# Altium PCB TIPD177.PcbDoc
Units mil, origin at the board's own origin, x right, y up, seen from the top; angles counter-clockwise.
Board outline 2500 x 3000 mil, 4 copper layers (Top Layer, Signal Layer 1, Signal Layer 2, Bottom Layer), stack 79.834 mil thick; 70 components, 24 nets, 146 pads, 48 vias.
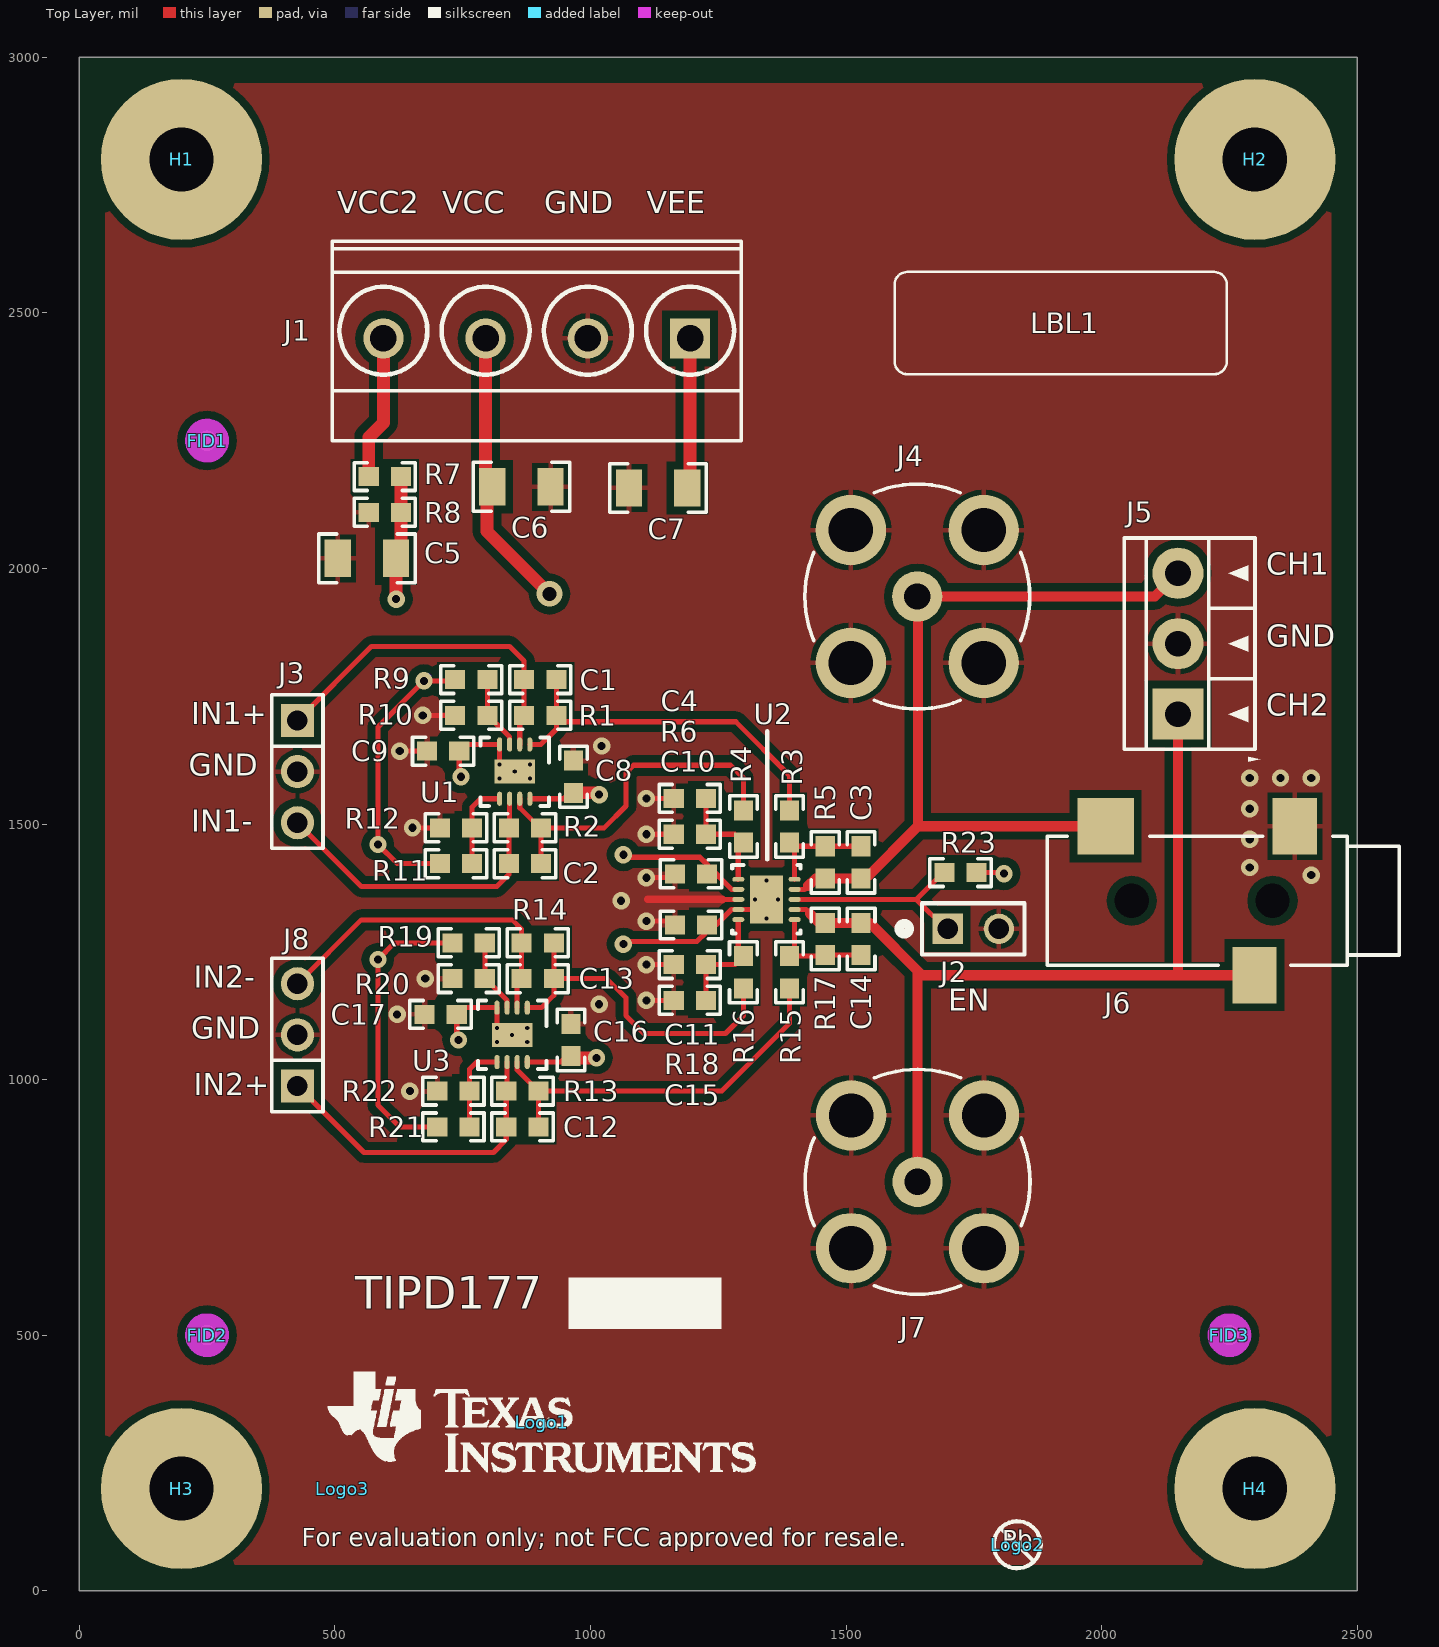
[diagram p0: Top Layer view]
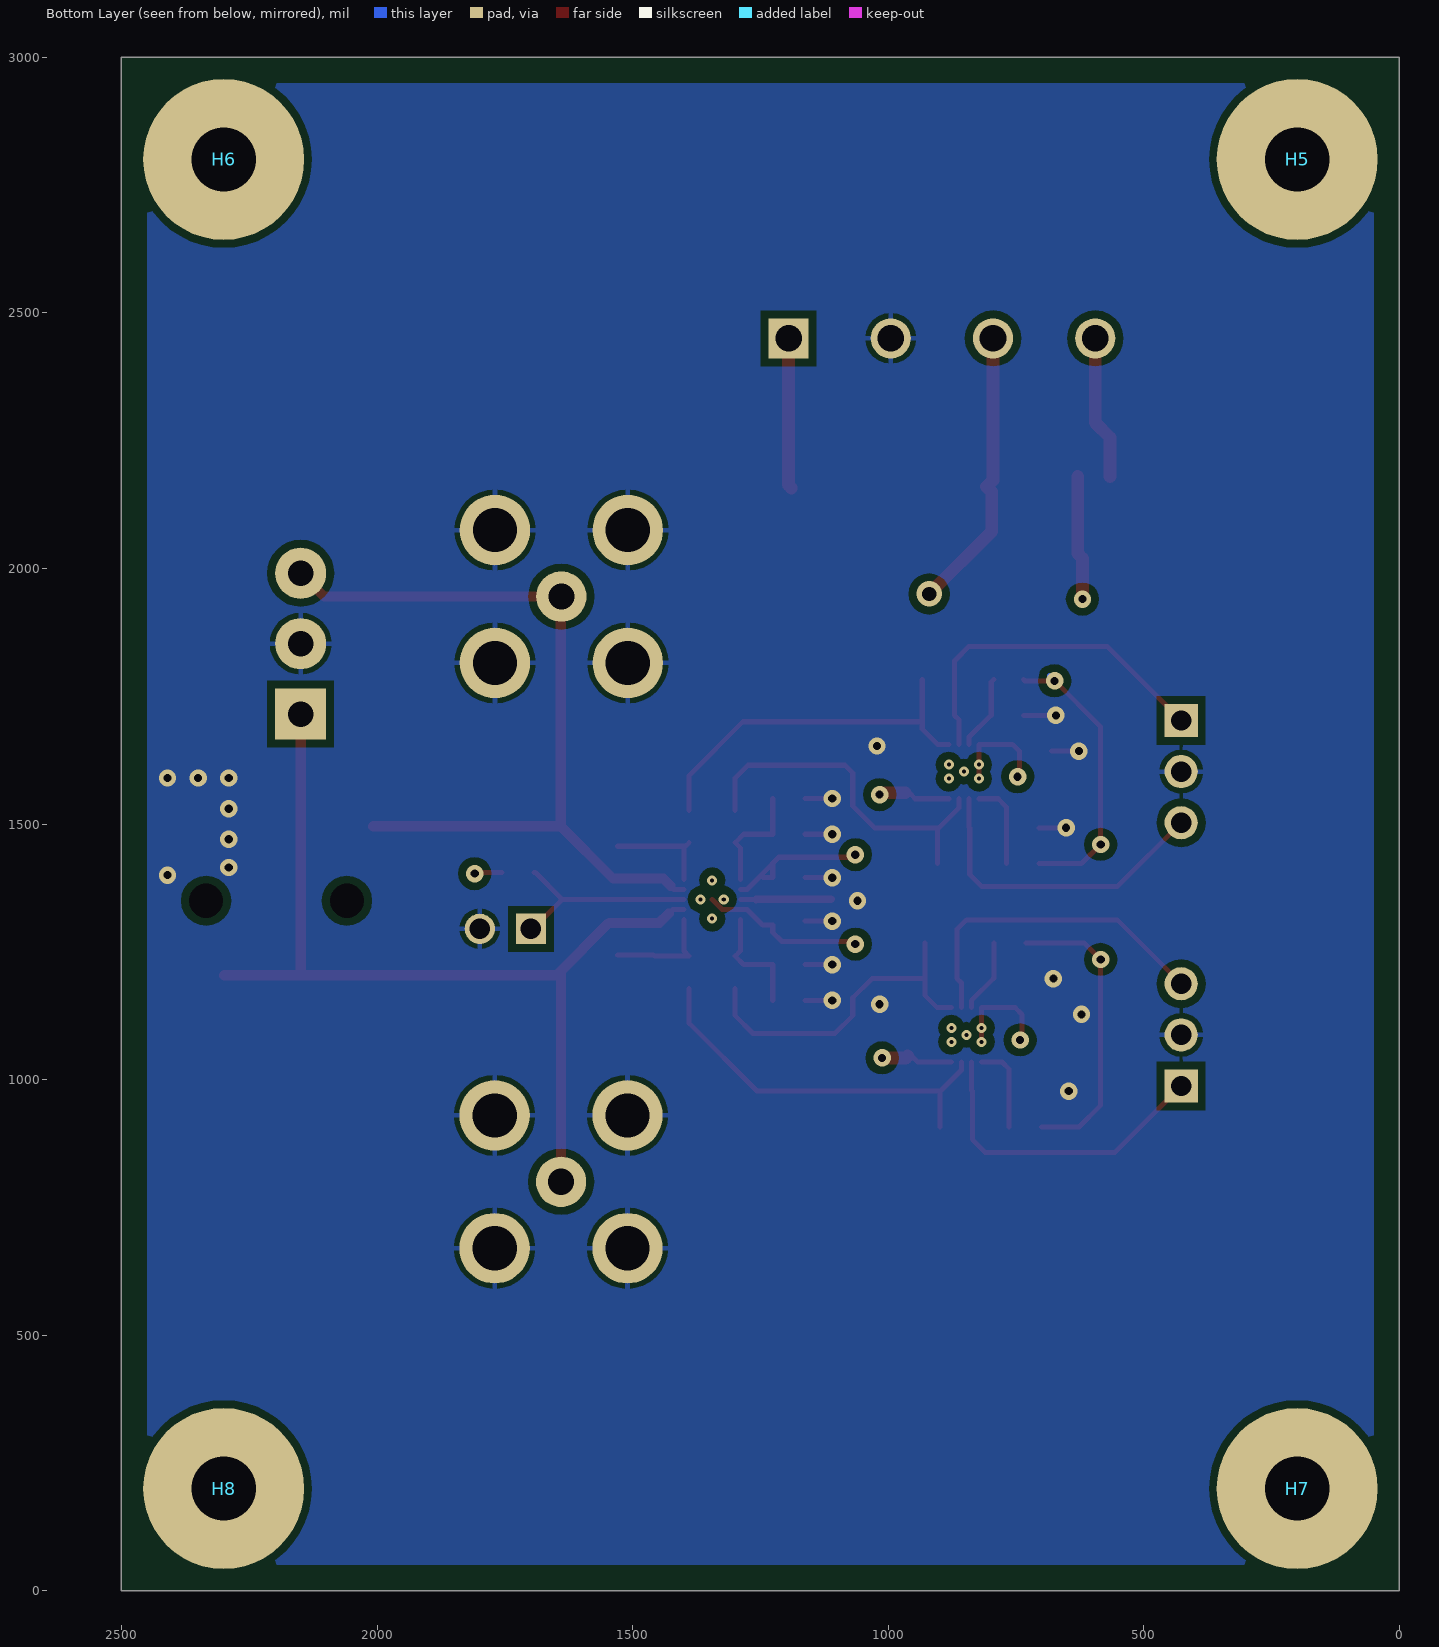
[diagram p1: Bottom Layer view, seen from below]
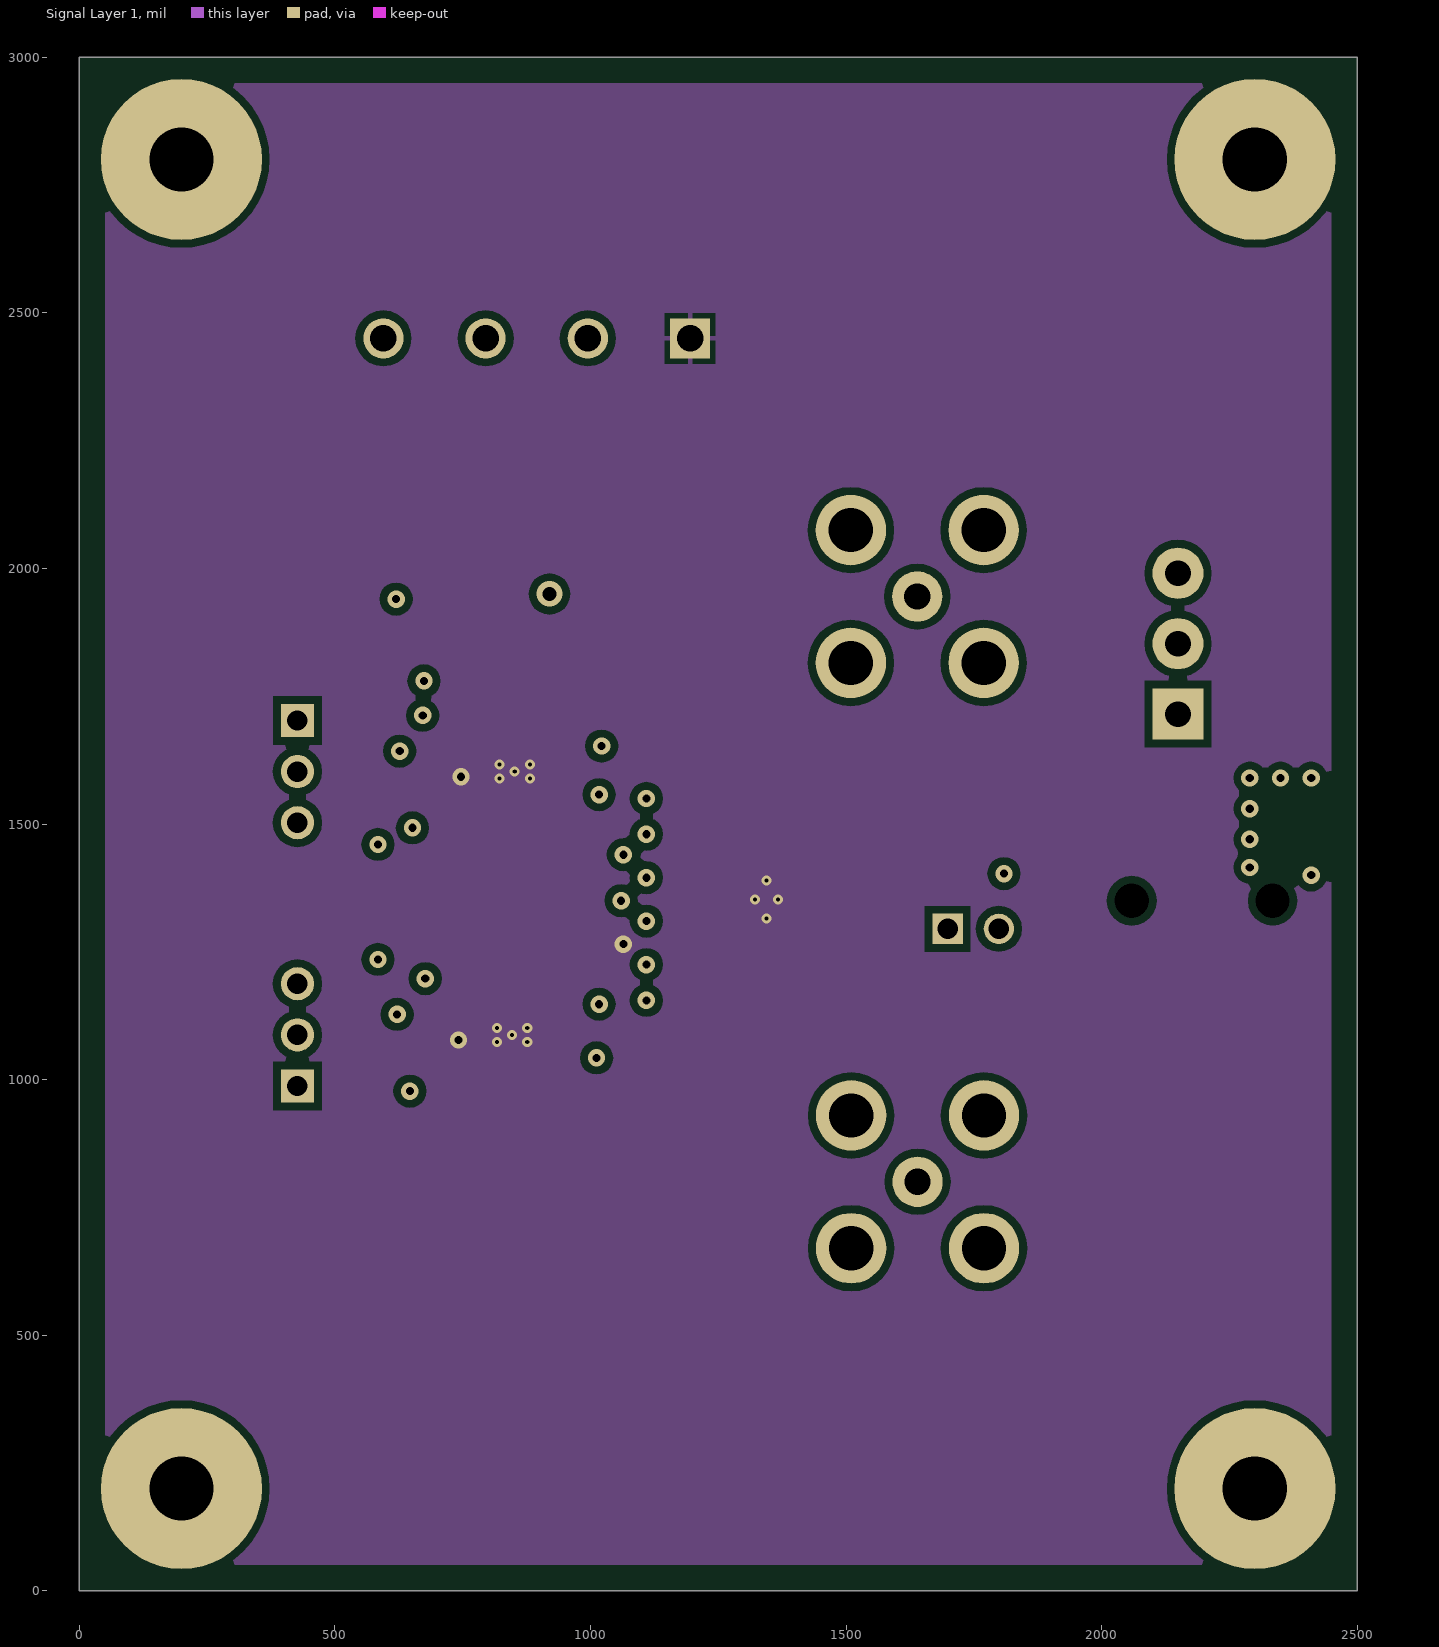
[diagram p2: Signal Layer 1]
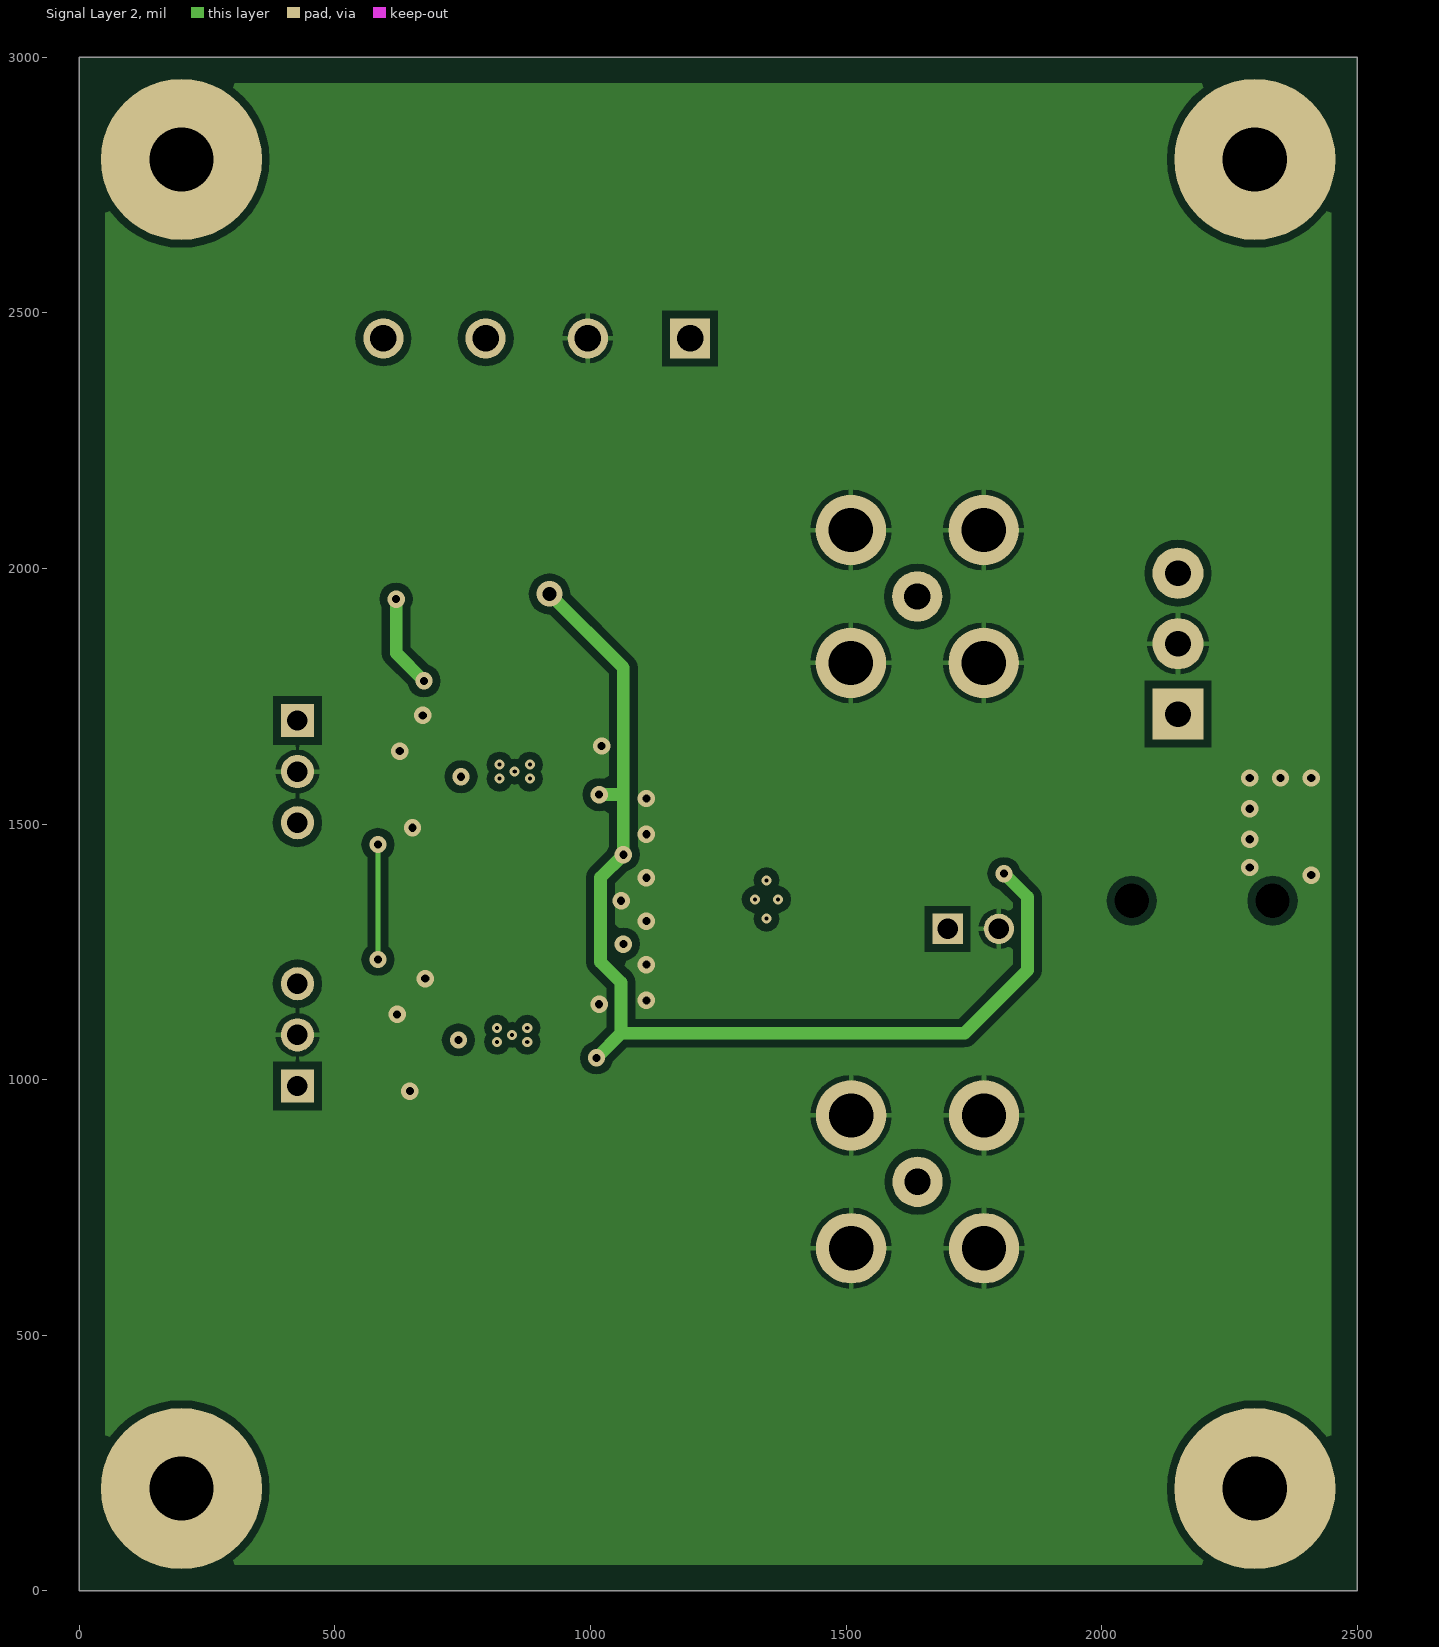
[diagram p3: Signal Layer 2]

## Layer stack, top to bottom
Top Solder: solder mask 0.4, Solder Resist, Dk 3.5
Top Layer: signal copper 1.4
Dielectric1: core 59.2, FR-4, Dk 4.8
Signal Layer 1: signal copper 1.417
Dielectric 3: prepreg 5, Dk 4.2
Signal Layer 2: signal copper 1.417
Dielectric 2: core 10, Dk 4.2
Bottom Layer: signal copper 1.4
Bottom Solder: solder mask 0.4, Solder Resist, Dk 3.5

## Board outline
0,0 0,3000 2500,3000 2500,0

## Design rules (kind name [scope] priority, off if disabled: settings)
AcuteAngle [All] p1: minimum=4.50000000000000E+0001 checktracksonly=FALSE
AssemblyTestPointUsage [All] p1: valid=2
BoardOutlineClearance BoardOutlineClearance_MountingHoles [OnCopper and InComponentClass('Mounting Holes')] p1: gap=40
BoardOutlineClearance BoardOutlineClearance_Poly [OnCopper and InPoly] p2: gap=25
BoardOutlineClearance [OnCopper and Not InComponentClass('Logo') and not InComponentClass('FiducialMark') and not InRegion(1000,500,4000,800)] p3: gap=50
Clearance Clearance_Keepouts [((IsTrack Or IsArc) And Not InPoly) And IsFree and IsKeepOut vs ((IsTrack Or IsArc) And Not InPoly) And IsFree and IsKeepOut] p1: gap=0
Clearance Clearance_Poly [InPolygon] p2: gap=15
Clearance [All] p3: gap=7.87
ComponentClearance ComponentClearance_MountingHoles_FiducialMarks [InComponentClass('Mounting Holes') vs InComponentClass('FiducialMark')] p1: gap=50 collisioncheckmode=3 verticalgap=10 showdistances=FALSE
ComponentClearance ComponentClearance_Shunt [InComponentClass('Header') vs InComponentClass('Shunt')] p2: gap=0 collisioncheckmode=3 verticalgap=0 showdistances=FALSE
ComponentClearance ComponentClearance_Logo [InComponentClass('Logo')] p3: gap=50 collisioncheckmode=3 verticalgap=10 showdistances=FALSE
ComponentClearance ComponentClearance_ScrewToNut [(HasFootprint('NY PMS 440 0025 PH')) vs (HasFootprint('Keystone_1902C'))] p4: gap=5 collisioncheckmode=3 verticalgap=10 showdistances=FALSE
ComponentClearance ComponentClearance_MountingHoles [InComponentClass('Mounting Holes')] p5: gap=100 collisioncheckmode=3 verticalgap=100000 showdistances=FALSE
ComponentClearance ComponentClearance_SmallPassives [HasFootprint('0201*') or HasFootprint('0402*') or HasFootprint('0508') or HasFootprint('0603*') or HasFootprint('0612') or HasFootprint('0805*') or HasFootprint('0815*') or HasFootprint('0830*') or HasFootprint('1206*') or HasFootprint('1210*') or HasFootprint('1808*') or HasFootprint('1812*') or HasFootprint('1825*') or HasFootprint('2010*') or HasFootprint('2220*') or HasFootprint('2225*') or HasFootprint('2512*') or HasFootprint('2728*') or HasFootprint('3518*') vs HasFootprint('0201*') or HasFootprint('0402*') or HasFootprint('0508') or HasFootprint('0603*') or HasFootprint('0612') or HasFootprint('0805*') or HasFootprint('0815*') or HasFootprint('0830*') or HasFootprint('1206*') or HasFootprint('1210*') or HasFootprint('1808*') or HasFootprint('1812*') or HasFootprint('1825*') or HasFootprint('2010*') or HasFootprint('2220*') or HasFootprint('2225*') or HasFootprint('2512*') or HasFootprint('2728*') or HasFootprint('3518*')] p6: gap=14.96 collisioncheckmode=3 verticalgap=10 showdistances=FALSE
ComponentClearance ComponentClearance_THtoSMT [IsThruComponent vs IsSMTComponent] p7: gap=40 collisioncheckmode=3 verticalgap=30 showdistances=FALSE
ComponentClearance ComponentClearance_THtoTH [IsThruComponent vs IsThruComponent] p8: gap=30 collisioncheckmode=3 verticalgap=30 showdistances=FALSE
ComponentClearance [All] p9: gap=30 collisioncheckmode=3 verticalgap=10 showdistances=FALSE
DiffPairsRouting [All] p1: maxlimit=100 minlimit=10 mostfreqgap=10 toplayer_minwidth=15 toplayer_maxwidth=15 toplayer_prefwidth=15 midlayer1_minwidth=15 midlayer1_maxwidth=15 midlayer1_prefwidth=15 midlayer2_minwidth=15 midlayer2_maxwidth=15 midlayer2_prefwidth=15 bottomlayer_minwidth=15 bottomlayer_maxwidth=15 bottomlayer_prefwidth=15 maxuncoupledlength=1000
FabricationTestPointUsage TestPointUsage [All] p1: valid=2 allowmultiple=FALSE
FabricationTestpoint Testpoint [All] p1: side=3 testpointundercomponent=TRUE minsize=40 maxsize=100 preferedsize=60 minholesize=0 maxholesize=40 preferedholesize=32 testpointgrid=1 allowsidetop=TRUE allowsidebottom=TRUE usegrid=TRUE gridtolerance=0.01
FanoutControl Fanout_LCC [IsLCC] p1: bgadir=Out bgaviamode=Centered fanoutstyle=Auto fanoutdirection=Alternating viagrid=1 // Fanout_LCC (Default Rule)
FanoutControl Fanout_BGA [IsBGA] p2: bgadir=Out bgaviamode=Centered fanoutstyle=Auto fanoutdirection=Alternating viagrid=1 // Fanout_BGA (Default Rule)
FanoutControl Fanout_Default [All] p4: bgadir=Out bgaviamode=Centered fanoutstyle=Auto fanoutdirection=Alternating viagrid=1 // Fanout_Default (Default Rule)
FanoutControl Fanout_Small [(CompPinCount < 5)] p5: bgadir=Out bgaviamode=Centered fanoutstyle=Auto fanoutdirection=OutThenIn viagrid=1 // Fanout_Small (Default Rule)
HoleSize [All] p1: absolutevalues=TRUE maxlimit=251 minlimit=7.87 maxpercent=80.000 minpercent=20.000
MinimumAnnularRing MinimumAnnularRing_ThermalPadVias [IsVia and InAnyComponent] p1: minimumring=5.91
MinimumAnnularRing [All] p2: minimumring=8
MinimumSolderMaskSliver MinimumSolderMaskSliver_Logo [InComponentClass('Logo') vs InComponentClass('Logo')] p1: minsoldermaskwidth=0.7
MinimumSolderMaskSliver [All] p2: minsoldermaskwidth=3.94
PlaneConnect [All] p1: planeconnectstyle=Relief reliefexpansion=10 reliefentries=4 reliefconductorwidth=10 reliefairgap=10
PolygonConnect PolygonConnect_2 [InComponent('U1','U2','U3')] p1: connectstyle=Direct reliefconductorwidth=10 reliefentries=4 polygonreliefangle="90 Angle" airgapwidth=10
PolygonConnect PolygonConnect_1 [InComponentClass('TIPD177_Main')] p2: connectstyle=Relief reliefconductorwidth=10 reliefentries=4 polygonreliefangle="90 Angle" airgapwidth=10
PolygonConnect [All] p3: connectstyle=Direct reliefconductorwidth=10 reliefentries=4 polygonreliefangle="90 Angle" airgapwidth=10
RoutingVias ThermalPadVias [IsVia and InAnyComponent] p1: holewidth=7.87 width=19.68 viastyle="Through Hole" minholewidth=7.87 minwidth=19.68 maxholewidth=12.99 maxwidth=23.62
RoutingVias [All] p2: holewidth=16 width=34 viastyle="Through Hole" minholewidth=7.87 minwidth=26 maxholewidth=40 maxwidth=65
SilkToBoardRegionClearance [Not ((IsComment or IsDesignator) And (Hide <> 'False')) and not InRegion(1000,500,4000,800)] p1:
SilkToSilkClearance SilkToSilkClearance_Pb-FreeLogo [(HasFootprint('Pb-Free_Overlay_Medium') OR HasFootprint('Pb-Free_Overlay_Small')) vs (HasFootprint('Pb-Free_Overlay_Medium') OR HasFootprint('Pb-Free_Overlay_Small'))] p1: silktosilkclearance=0
SilkToSilkClearance [All] p2: silktosilkclearance=4
SilkToSolderMaskClearance SilkToComponentPadClearance [IsPad and InAnycomponent] p1: minsilkscreentomaskgap=5 clearancetoexposedcopper=TRUE
SilkToSolderMaskClearance "Silk to Solder Mask Opening" [All] p2: minsilkscreentomaskgap=4 clearancetoexposedcopper=FALSE
SolderMaskExpansion [All] p1: expansion=1.97
Width [All] p1: maxlimit=100 minlimit=6 preferedwidth=10 checkconnectedcopper=TRUE
15 further rules are at their usual default settings.

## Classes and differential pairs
component class TIPD177_Main: C1 C2 C3 C4 C5 C6 C7 C8 C9 C10 C11 C12 C13 C14 C15 C16 C17 J1 J2 J3 J4 J5 J6 J7 J8 R1 R2 R3 R4 R5 R6 R7 R8 R9 R10 R11 R12 R13 R14 R15 R16 R17 R18 R19 R20 R21 R22 R23 U1 U2 U3
component class Header: J2 J3 J8
component class Label: LBL1
component class AssemblyNote: ZZ1 ZZ2 ZZ3 ZZ4
component class FiducialMark: FID1 FID2 FID3
component class TIPD177_Hardware: FID1 FID2 FID3 H1 H2 H3 H4 H5 H6 H7 H8 LBL1 Logo1 Logo2 Logo3 ZZ1 ZZ2 ZZ3 ZZ4
component class Logo: Logo1
component class "Mounting Holes": H1 H2 H3 H4

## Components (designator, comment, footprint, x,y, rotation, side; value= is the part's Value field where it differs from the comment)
C1 "GRM1885C1H101JA01D" 0603 901.93,1782.5 r180 top
C2 "GRM1885C1H101JA01D" 0603 871.93,1422.5 r180 top
C3 "GRM1885C1H561JA01D" 0603 1529.43,1425 r90 top
C4 "GRM1885C1H561JA01D" 0603 1194.43,1550 r0 top
C5 "GRM316R61E225KA12D" 1206 562.76,2019.69 r180 top
C6 "C3216X5R1C106M" 1206 865,2159.69 r0 top
C7 "C3216X5R1C106M" 1206 1132.5,2157.5 r180 top
C8 "GRM188R71H104KA93D" 0603 966.93,1592.5 r270 top
C9 "GRM188R71H104KA93D" 0603 711.93,1642.5 r0 top
C10 "GRM188R71H104KA93D" 0603 1196.93,1402.5 r180 top
C11 "GRM188R71H104KA93D" 0603 1196.93,1302.5 r180 top
C12 "GRM1885C1H101JA01D" 0603 866.93,907.5 r180 top
C13 "GRM1885C1H101JA01D" 0603 896.93,1197.5 r180 top
C14 "GRM1885C1H561JA01D" 0603 1529.43,1275 r270 top
C15 "GRM1885C1H561JA01D" 0603 1194.43,1155 r0 top
C16 "GRM188R71H104KA93D" 0603 961.93,1077.5 r270 top
C17 "GRM188R71H104KA93D" 0603 706.93,1127.5 r0 top
FID1 "Fiducial" Fiducial10-20 250,2250 r0 top
FID2 "Fiducial" Fiducial10-20 250,500 r0 top
FID3 "Fiducial" Fiducial10-20 2250,500 r0 top
H1 "NY PMS 440 0025 PH" "NY PMS 440 0025 PH" 200,2800 r0 top
H2 "NY PMS 440 0025 PH" "NY PMS 440 0025 PH" 2300,2800 r0 top
H3 "NY PMS 440 0025 PH" "NY PMS 440 0025 PH" 200,200 r0 top locked
H4 "NY PMS 440 0025 PH" "NY PMS 440 0025 PH" 2300,200 r0 top
H5 "1902C" Keystone_1902C 200,2800 r180 bottom locked
H6 "1902C" Keystone_1902C 2300,2800 r180 bottom locked
H7 "1902C" Keystone_1902C 200,200 r180 bottom locked
H8 "1902C" Keystone_1902C 2300,200 r180 bottom locked
J1 "39544-3004" MOLEX_39544-3004 895,2450 r180 top
J2 "5-146261-1" CONN_5-146261-1 1749,1295 r0 top
J3 "PBC03SAAN" PBC03SAAN 426.93,1602.5 r270 top
J4 "112404" Amphenol_112404 1639.43,1945 r0 top
J5 "ED555/3DS" TERM_BLK_ED555-3DS 2149.43,1715 r90 top
J6 "SJ-3523-SMT" CUI_SJ-3523-SMT 2192.85,1350 r180 top
J7 "112404" Amphenol_112404 1640,800 r0 top
J8 "PBC03SAAN" PBC03SAAN 426.93,1087.5 r90 top
LBL1 "Size: 0.65\" x 0.20 \"" Label_650x200 1920,2480 r0 top
Logo1 "Texas Instruments" TI_Stacked_Overlay_Small 905,330 r0 top
Logo2 "Pb-Free Symbol" Pb-Free_Overlay_Small 1835,90 r0 top
Logo3 "FCC disclaimer" FCC_disclaimer 515,200 r0 top
R1 "RT0603BRD072K32L" 0603 901.93,1712.5 r0 top
R2 "RT0603BRD072K32L" 0603 871.93,1492.5 r0 top
R3 "RT0603BRD071K58L" 0603 1389.43,1495 r270 top
R4 "RT0603BRD071K58L" 0603 1299.43,1495 r270 top
R5 "RG1608P-561-B-T5" 0603 1459.43,1425 r270 top
R6 "RG1608P-561-B-T5" 0603 1194.43,1480 r180 top
R7 "RT0603BRD0724K9L" 0603 597.76,2179.69 r180 top
R8 "RT0603BRD0714K7L" 0603 597.76,2109.69 r0 top
R9 "CRCW06030000Z0EA" 0603 766.93,1782.5 r180 top
R10 "CRCW06030000Z0EA" 0603 766.93,1712.5 r0 top
R11 "CRCW06030000Z0EA" 0603 736.93,1422.5 r180 top
R12 "CRCW06030000Z0EA" 0603 736.93,1492.5 r0 top
R13 "RT0603BRD072K32L" 0603 866.93,977.5 r0 top
R14 "RT0603BRD072K32L" 0603 896.93,1267.5 r0 top
R15 "RT0603BRD071K58L" 0603 1389.43,1210 r90 top
R16 "RT0603BRD071K58L" 0603 1299.43,1210 r90 top
R17 "RG1608P-561-B-T5" 0603 1459.43,1275 r90 top
R18 "RG1608P-561-B-T5" 0603 1194.43,1225 r180 top
R19 "CRCW06030000Z0EA" 0603 761.93,1267.5 r180 top
R20 "CRCW06030000Z0EA" 0603 761.93,1197.5 r0 top
R21 "CRCW06030000Z0EA" 0603 731.93,907.5 r180 top
R22 "CRCW06030000Z0EA" 0603 731.93,977.5 r0 top
R23 "CRCW060310K0FKEA" 0603 1724,1405 r0 top
U1 "OPA1612AIDRGR" DRG0008A 851.93,1602.5 r270 top
U2 "OPA1622IDRCR" DRC0010J 1344.43,1352.4 r0 top
U3 "OPA1612AIDRGR" DRG0008A 846.93,1087.5 r270 top
ZZ1 "This Assembly Note is for PCB labels only" AssemblyNoteLabel 185,3938 r0 top
ZZ2 "These assemblies are ESD sensitive, ESD precautions shall be observed." AssemblyNote 185,3829.11 r0 top
ZZ3 "These assemblies must be clean and free from flux and all contaminants. Use of no clean flux is not acceptable." AssemblyNote 185,3740.56 r0 top
ZZ4 "These assemblies must comply with workmanship standards IPC-A-610 Class 2, unless otherwise specified." AssemblyNote 185,3652 r0 top

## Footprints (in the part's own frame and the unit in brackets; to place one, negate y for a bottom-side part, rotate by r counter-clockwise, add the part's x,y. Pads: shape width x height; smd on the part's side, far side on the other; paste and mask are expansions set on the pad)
0603 [mm] "0603 from SM-752 data"
  rect 1x0.95 smd: 1(-0.8,0) 2(0.8,0)
  silkscreen extent -1.52,-0.69 1.52,0.69, body extent -0.87,-0.47 0.87,0.47, height 1
1206 [mm] "1206 from SM-752 data"
  rect 1.3x1.85 smd: 1(-1.45,0) 2(1.45,0)
  silkscreen extent -2.4,-1.21 2.4,1.21, body extent -1.7,-0.9 1.7,0.9, height 1.35
Amphenol_112404 [mm] "BNC footprint, pins compatible with Amp 5413631-2"
  round 2.5 hole 1.3: 1(0,0)
  round 3.5 hole 2.2: 2(-3.3,3.3) 3(3.3,3.3) 4(3.3,-3.3) 5(-3.3,-3.3)
  silkscreen extent -5.59,-5.59 5.59,5.59, body extent -5.5,-5.5 5.5,5.5, height 13.7
AssemblyNote [mil] "Assembly Note"
AssemblyNoteLabel [mil] "Assembly Note for PCB Labels"
CONN_5-146261-1 [mm] "Sullins"
  rect 1.5x1.5 hole 1.02: 1(-1.27,0)
  round 1.5 hole 1.02: 2(1.27,0)
  silkscreen extent -3.68,-1.27 2.54,1.27, body extent -2.51,-1.27 2.51,1.27, height 10.87
CUI_SJ-3523-SMT [mm] "CUI recommended land pattern Rev C CUI_SJ-3523-SMT_Datasheet.pdf"
  rect 2.2x2.8 smd: 1(-4.7,-3.7) 3(-2.7,3.7)
  rect 2.8x2.8 smd: 2(4.7,-3.7)
  round 0 hole 1.7 unplated: 4(-3.6,0) 5(3.4,0)
  silkscreen extent -9.9,-3.2 7.6,3.2, body extent -9.6,-4.5 7.4,4.5, height 5.12
DRC0010J [mm] "SON, 10-Leads, Body 3x3mm, Pitch 0.5mm, Thermal Pad 2.4x1.65mm, TI Recommended"
  rrect100% 0.6x0.24 smd: 1(-1.4,1) 2(-1.4,0.5) 3(-1.4,0) 4(-1.4,-0.5) 5(-1.4,-1) 6(1.4,-1) 7(1.4,-0.5) 8(1.4,0) 9(1.4,0.5) 10(1.4,1)
  rrect6% 1.65x2.4 smd paste-0.825: 11(0,0)
  silkscreen extent -1.7,-1.7 1.7,1.7, body extent -1.5,-1.5 1.5,1.5, height 0.77
DRG0008A [mm] "SON, 8-Leads, Body 3x3mm, Pitch 0.5mm, Thermal Pad 2x1.2mm, TI Recommended"
  oval 0.7x0.25 smd: 1(-1.35,0.75) 2(-1.35,0.25) 3(-1.35,-0.25) 4(-1.35,-0.75) 5(1.35,-0.75) 6(1.35,-0.25) 7(1.35,0.25) 8(1.35,0.75)
  rect 1.2x2 smd paste-0.6: 9(0,0)
  Drill Guide keep-out region: 0.6,-1.001 -0.6,-1.001 -0.6,-1.301 0.6,-1.301
  Drill Guide keep-out region: -0.6,0.999 0.6,0.999 0.6,1.299 -0.6,1.299
  silkscreen extent -1.7,-1.7 1.7,1.7, body extent -1.55,-1.55 1.55,1.55, height 0.81
FCC_disclaimer [mil]
Fiducial10-20 [mm]
  round 1 smd mask+0.5: 1(0,0)
  Top Layer keep-out circle w1.178: c0,0 r0.5
Keystone_1902C [mil] "Hex Standoff, 4-40 threaded, nylon"
  body extent -145,-126 146,126, height 501
Label_650x200 [mil] "Thermal Transfer Label"
  silkscreen extent -325,-100 325,100, body extent -325,-100 325,100, height 1
MOLEX_39544-3004 [mm] "Molex"
  rect 2x2 hole 1.321: 1(-7.62,0)
  round 2 hole 1.321: 2(-2.54,0) 3(2.54,0) 4(7.62,0)
  silkscreen extent -10.16,-4.83 10.16,5.08, body extent -10.16,-4.83 10.16,5.08, height 14.49
"NY PMS 440 0025 PH" [mm] "4-40 nylon screw and mounting hole"
  round 8 hole 3.2: 1(0,0)
  body extent -3.3,-3.3 3.3,3.3, height 2.69
Pb-Free_Overlay_Small [mil]
  silkscreen extent -46,-46 46,46
PBC03SAAN [mm] "Sullins 100mil, 1x3, 230 mil above insulator"
  rect 1.65x1.65 hole 1.016: 1(-2.54,0)
  round 1.65 hole 1.016: 2(0,0) 3(2.54,0)
  silkscreen extent -3.81,-1.27 3.81,1.27, body extent -3.81,-1.27 3.81,1.27, height 8.38
TERM_BLK_ED555-3DS [mm]
  rect 2.54x2.54 hole 1.27: 1(0,0)
  round 2.54 hole 1.27: 2(3.5,0) 3(7,0)
  silkscreen extent -2.36,-4.09 8.75,2.67, body extent -1.75,-3.83 8.75,2.67, height 8.2
TI_Stacked_Overlay_Small [mil]
  silkscreen extent -418,-98 418,98

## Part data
C1 C2 C12 C13: "CAP, CERM, 100 pF, 50 V, +/- 5%, C0G/NP0, 0603"
C3 C4 C14 C15: "CAP, CERM, 560 pF, 50 V, +/- 5%, C0G/NP0, 0603"
C5: "CAP, CERM, 2.2uF, 25V, +/-10%, X5R, 1206"
C6 C7: "CAP, CERM, 10uF, 16V, +/-20%, X5R, 1206"
C8 C9 C10 C11 C16 C17: "CAP, CERM, 0.1 µF, 50 V, +/- 10%, X7R, 0603"
FID1 FID2 FID3: "Fiducial mark.  There is nothing to buy or mount."
H1 H2 H3 H4: "Machine Screw, Round, #4-40 x 1/4, Nylon, Philips panhead"
H5 H6 H7 H8: "Standoff, Hex, 0.5\"L #4-40 Nylon"
J1: "Terminal Block, 4x1, 5.08mm, TH"
J2: "Header, 100mil, 2x1, Gold, TH"
J3 J8: "Header, 100mil, 3x1, Gold, TH"
J4 J7: "Connector, TH, BNC"
J5: "Terminal Block, 3.5mm Pitch, 3x1, TH"
J6: "Audio Jack, 3.5mm, Stereo, R/A, SMT"
LBL1: library part THT-14-423-10, "Thermal Transfer Printable Labels, 0.650\" W x 0.200\" H - 10,000 per roll"
Logo1: library part TI_Logo, "Texas Instrument Corporate Signature"
Logo2: library part Pb-Free
Logo3: library part FCC_disclaimer, "FCC_disclaimer"
R1 R2 R13 R14: "RES, 2.32 k, 0.1%, 0.1 W, 0603"
R3 R4 R15 R16: "RES, 1.58 k, 0.1%, 0.1 W, 0603"
R5 R6 R17 R18: "RES, 560, 0.1%, 0.1 W, 0603"
R7: "RES, 24.9 k, 0.1%, 0.1 W, 0603"
R8: "RES, 14.7 k, 0.1%, 0.1 W, 0603"
R9 R10 R11 R12 R19 R20 R21 R22: "RES, 0, 5%, 0.1 W, 0603"
R23: "RES, 10.0k ohm, 1%, 0.1W, 0603"
U1 U3: "SoundPlus High-Performance, Bipolar-Input Audio Operational Amplifiers, DRG0008A"
U2: "SoundPlus High-Fidelity, Bipolar-Input, Audio Operational Amplifier, DRC0010J"
ZZ1: library part AssemblyNoteLabel
ZZ2 ZZ3 ZZ4: library part AssemblyNote

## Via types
v1: diameter 34, hole 16, Top Layer to Bottom Layer, 33 vias
v2: diameter 19.68, hole 8, Top Layer to Bottom Layer, 14 vias
v3: diameter 50, hole 28, Top Layer to Bottom Layer, 1 vias

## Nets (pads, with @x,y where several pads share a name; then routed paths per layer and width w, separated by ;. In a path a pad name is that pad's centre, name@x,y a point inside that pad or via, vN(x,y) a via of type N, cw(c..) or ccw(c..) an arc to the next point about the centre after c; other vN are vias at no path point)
EN: J2.1 R23.1 U2.8 | length 395.9
  Top Layer w10: U2.8 1637.6,1352.4 ; R23.1 1690.2,1405 1637.6,1352.4 ; J2.1@1695,1295 1637.6,1352.4
GND: C4.1 C5.2 C6.2 C7.2 C8.1 C9.1 C10.2 C11.2 C15.1 C16.1 C17.1 J1.2 J2.2 J3.2 J4.2 J4.3 J4.4 J4.5 J5.2 J6.1 J7.2 J7.3 J7.4 J7.5 J8.2 R6.2 R8.1 R10.1 R12.1 R18.2 R20.1 R22.1 U2.3 | length 779.1
  Top Layer w10: v1(626.93,1642.5) C9.1 ; v1(651.93,1492.5) R12.1 ; v1(671.93,1712.5) R10.1 ; v1(1109.43,1155) C15.1 ; v1(1109.43,1225) R18.2 ; v1(1109.43,1310) C11.2@1162.93,1310 ; v1(1109.43,1395) C10.2@1162.93,1395 ; v1(1109.43,1480) R6.2 ; v1(1109.43,1550) C4.1 ; 1111.93,1352.5 1112.03,1352.4 1221.93,1352.4 ; 1258.02,1352.4 U2.3
  Top Layer w15: 1111.93,1352.5 1258.02,1352.4 1258.12,1352.5
  other v1: 646.93,977.5 621.93,1127.5 1016.93,1147.5 676.93,1197.5 1060,1350 2410,1400 2290,1415 2290,1470 2290,1530 2290,1590 2350,1590 2410,1590 1021.93,1652.5
NetC1_1: C1.1 R1.2 R3.1 U1.1 | length 726.5
  Top Layer w10: U1.1 903.08,1655.65 933.42,1686 R1.2 C1.1 ; R1.2@935.92,1700 1284.43,1700 1389.43,1595 R3.1
NetC1_2: C1.2 J3.1 R1.1 U1.2 | length 682.3
  Top Layer w10: J3.1 571.93,1847.5 841.93,1847.5 870.43,1819 R1.1 861.77,1703.84 U1.2
NetC2_1: C2.1 R2.2 R4.1 U1.7 | length 704.2
  Top Layer w10: U1.7 861.77,1531.66 900.93,1492.5 R2.2 ; C2.1 R2.2 ; R4.1 1299.43,1590 1274.43,1615 1084.43,1615 1069.43,1600 1069.43,1535 1026.93,1492.5 R2.2
NetC2_2: C2.2 J3.3 R2.1 U1.6 | length 624
  Top Layer w10: J3.3 551.93,1377.5 816.93,1377.5 840.43,1401 C2.2 R2.1 842.09,1494.15 U1.6
NetC3_1: C3.1 J4.1 J5.3 J6.2 R5.2 U2.9 | length 1647.3
  Top Layer w10: U2.9 1418.91,1372.09 1425.91,1379.09
  Top Layer w20: 1425.91,1379.09 1440.32,1393.5 R5.2 C3.1@1538.5,1393.5 ; C3.1 C3.1@1538.5,1393.5 ; J6.2 1640.67,1495.67 ; J5.3 2103.84,1945 J4.1 1640.67,1943.76 1640.67,1495.67 ; C3.1@1538.5,1393.5 1640.67,1495.67
NetC3_2: C3.2 R3.2 R5.1 U2.10 | length 208.9
  Top Layer w10: R3.2 R3.2@1396.44,1456.5 ; U2.10 1399.55,1453.39 R3.2@1396.44,1456.5 ; C3.2 R5.1 R3.2@1396.44,1456.5
NetC4_2: C4.2 R4.2 R6.1 U2.1 | length 226.3
  Top Layer w10: C4.2 R6.1 1282.93,1480 R4.2 1289.31,1453.39 U2.1
NetC12_1: C12.1 R13.2 R15.1 U3.7 | length 758.8
  Top Layer w10: U3.7 856.77,1018.66 897.93,977.5 R13.2 ; C12.1 R13.2 ; R15.1 1389.43,1110 1256.93,977.5 R13.2
NetC12_2: C12.2 J8.1 R13.1 U3.6 | length 625.1
  Top Layer w10: J8.1 556.93,857.5 810.19,857.5 835.43,882.74 R13.1 837.09,979.15 U3.6
NetC13_1: C13.1 R14.2 R16.1 U3.1 | length 668.6
  Top Layer w10: U3.1 904.08,1140.65 928.42,1165 C13.1 ; R14.2 C13.1 ; R16.1 1299.43,1125 1264.43,1090 1104.43,1090 1069.43,1125 1069.43,1160 1031.93,1197.5 C13.1
NetC13_2: C13.2 J8.3 R14.1 U3.2 | length 654.9
  Top Layer w10: J8.3 551.93,1312.5 846.93,1312.5 865.43,1294 R14.1 C13.2 856.77,1188.84 U3.2
NetC14_1: C14.1 J5.1 J6.3 J7.1 R17.2 U2.7 | length 1873.7
  Top Layer w10: U2.7 1421.71,1332.72 1429.43,1325 ; 2149.43,1204.9 2150,1204.33
  Top Layer w20: 1429.43,1325 1447.93,1306.5 R17.2 C14.1 1546.48,1306.5 1648.64,1204.33 2150,1204.33 J6.3 ; J7.1 1640,1210 ; 2149.43,1204.9 J5.1
NetC14_2: C14.2 R15.2 R17.1 U2.6 | length 216.6
  Top Layer w10: U2.6 1399.55,1251.61 R15.2 1457.42,1241.5 R17.1 C14.2
NetC15_2: C15.2 R16.2 R18.1 U2.5 | length 226.1
  Top Layer w10: C15.2 R18.1 1282.93,1225 R16.2 1289.31,1251.61 U2.5
NetJ1_4: J1.4 R7.2 | length 282.2
  Top Layer w25: R7.2 566.26,2256.26 595,2285 J1.4
NetR9_1: R9.1 R10.2 U1.3 | length 147.7
  Top Layer w10: R9.1@793.42,1782.5 798.42,1777.5 R10.2 799.58,1712.5 842.09,1669.99 U1.3
NetR11_1: R11.1 R12.2 U1.5 | length 171.2
  Top Layer w10: R11.1 R12.2 768.42,1533 784.78,1549.35 U1.5
NetR19_1: R19.1 R20.2 U3.3 | length 145.6
  Top Layer w10: R19.1 R20.2 794.58,1197.5 837.09,1154.99 U3.3
NetR21_1: R21.1 R22.2 U3.5 | length 172.5
  Top Layer w10: R21.1 R22.2 763.42,1020.14 777.64,1034.35 U3.5
VB: C5.1 R7.1 R8.2 R9.2 R11.2 R19.2 R21.2 | length 1799
  Top Layer w10: R21.2 626.93,907.5 584.43,950 v1(584.43,1235) 616.93,1267.5 R19.2 ; R11.2 621.93,1422.5 v1(584.43,1460) 584.43,1690 v1(674.43,1780) 732.93,1780 R9.2
  Top Layer w25: v1@619.84,1940.16 C5.1 629.25,2029.09 R8.2 R7.1
  Signal Layer 2 w10: v1(584.43,1235) v1(584.43,1460)
  Signal Layer 2 w25: v1(620,1940) 620,1834.43 v1(674.43,1780)
  Bottom Layer w10: v1(674.43,1780) v1@684.43,1790
VCC: C6.1 C8.2 C10.1 C16.2 J1.3 R23.2 U1.8 U2.2 U3.8 | length 3328.7
  Top Layer w10: U3.8 942.28,1034.35 C16.2@955.43,1047.5 ; U1.8 947.28,1549.35 C8.2@960.43,1562.5 ; v1(1064.43,1440) 1069.43,1435 1213.43,1435 ; C10.1@1244.43,1395 1225.92,1395 1225.92,1422.5 ; U2.2 1276.34,1372.09 1225.92,1422.5 ; R23.2 1807,1405 v1(1809,1403) ; 1213.43,1435 1214.43,1435 1225.92,1423.5 1225.92,1422.5 ; 1213.43,1435 1225.92,1422.5
  Top Layer w25: J1.3 795,2172.6 C6.1 797.5,2149.27 797.5,2072.5 v3(920,1950) ; C16.2 965.43,1042.5 v1(1011.93,1042.5) ; C8.2 1013.42,1561 v1(1016.93,1557.5)
  Signal Layer 2 w25: v3(920,1950) 1064.43,1805.57 1064.43,1555 ; v1(1011.93,1042.5) 1060,1090.57 ; v1(1016.93,1557.5) 1061.93,1557.5 1064.43,1555 ; v1(1809,1403) 1855,1357 1855,1214 1731.57,1090.57 1060,1090.57 ; 1060,1090.57 1060,1190 1020,1230 1020,1395.57 v1(1064.43,1440) 1064.43,1555
VEE: C7.1 C9.2 C11.1 C17.2 J1.1 U1.4 U1.9 U2.4 U2.11 U3.4 U3.9 | length 1022.6
  Top Layer w10: v1(741.93,1077.5) 738.42,1081 C17.2 751.57,1140.65 U3.4 817.4,1117.03 v2(817.4,1073.72) ; v1(746.93,1592.5) 743.42,1596 C9.2 756.57,1655.65 U1.4 822.4,1632.03 v2(822.4,1588.72) ; v1(1064.43,1265) 1069.43,1270 1207.97,1270 1225.92,1287.95 C11.1@1225.92,1302.5 ; C11.1 1245.93,1302.5 1276.15,1332.72 U2.4 1324.74,1332.72 U2.11
  Top Layer w25: C7.1 1195,2162.91 J1.1
  other v2: 876.46,1073.72 846.93,1087.5 817.4,1101.28 876.46,1101.28 1344.43,1315 1321.79,1352.4 1367.07,1352.4 1344.43,1389.8 881.46,1588.72 851.93,1602.5 822.4,1616.28 881.46,1616.28
pads on no net: FID1.1 FID2.1 FID3.1 H1.1 H2.1 H3.1 H4.1 J6.4 J6.5

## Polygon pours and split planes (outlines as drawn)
VEE on Signal Layer 1 "SIGNAL_LAYER_1_VEE_P000" (solid, remove dead copper, pour order 0): 0,3000 2500,3000 2500,0 0,0
GND on Top Layer "TOP_LAYER_GND_P006" (solid, remove dead copper, pour order 6): 0,3000 2500,3000 2500,0 0,0
GND on Bottom Layer "BOTTOM_LAYER_GND_P004" (solid, remove dead copper, pour order 4): 0,3000 2500,3000 2500,0 0,0
GND on Signal Layer 2 "SIGNAL_LAYER_2_GND_P002" (solid, remove dead copper, pour order 2): 0,3000 2500,3000 2500,0 0,0

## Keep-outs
Keep-Out Layer:
  text ".Layer_Name" at 577,-858.49 h60

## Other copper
Top Layer:
  text ".Layer_Name" at 577,-858.49 h60
Bottom Layer:
  text ".Layer_Name" at 577,-858.49 h60

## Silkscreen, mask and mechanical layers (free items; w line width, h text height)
Top Overlay:
  region: 1256.93,612.5 956.93,612.5 956.93,512.5 1256.93,512.5
  lines w8: 1345.93,1430.5 1345.93,1681.5
  text "VCC2" at 505,2680 h72.83
  text "VCC" at 710,2680 h72.83
  text "GND" at 910,2680 h72.83
  text "VEE" at 1110,2680 h72.83
  text "CH1" at 2321.93,1972.5 h72.83
  text "GND" at 2321.93,1832.5 h72.83
  text "CH2" at 2321.93,1697.5 h72.83
  text "IN1+" at 219.43,1680 h72.83
  text "GND" at 214.43,1580 h72.83
  text "IN1-" at 219.43,1470 h72.83
  text "IN2-" at 224.43,1165 h72.83
  text "EN" at 1700,1120 h72.83
  text "GND" at 219.43,1065 h72.83
  text "IN2+" at 224.43,955 h72.83
  text "TIPD177" at 540,530 h108.27
  text ".Layer_Name" at 577,-858.49 h60
Bottom Overlay:
  text ".Layer_Name" at 577,-858.49 h60
Top Paste:
  text ".Layer_Name" at 577,-858.49 h60
Bottom Paste:
  text ".Layer_Name" at 577,-858.49 h60
Top Solder:
  text ".Layer_Name" at 577,-858.49 h60
  text ".Layer_Name" at 577,-858.49 h60
Bottom Solder:
  text ".Layer_Name" at 577,-858.49 h60
Drill Guide:
  text ".Layer_Name" at 577,-858.49 h60
M1 Board Outline:
  the board outline again, w10
  text ".Layer_Name" at 577,-858.49 h60
M2 Board Dimensions:
  rectangle: 125,-400 500,-275
  rectangle: 0,-275 125,-150
  lines w7: 0,-275 1000,-275 ; 125,-400 125,-150 ; 250,-400 250,-150 ; 500,-400 500,-150 ; 750,-400 750,-150 ; 0,-400 0,-150 1000,-150 1000,-400 0,-400
  text ".Layer_Name" at 577,-858.49 h60
M3 3D STEP Top:
  text ".Layer_Name" at 577,-858.49 h60
M4 3D STEP Bottom:
  text ".Layer_Name" at 577,-858.49 h60
M5 Assembly Top:
  lines w10: -292,-930.17 6308,-930.17 ; -292,-726.83 6310,-726.83 ; -292,-523.5 -292,-1133.5 3713,-1133.5 6310,-1133.5 6310,-523.5 -291.5,-523.5 -291.5,-1133.5 1284,-1133.5 ; 2173,-1133.5 2173,-523.5 ; 3440,-726.83 3440,-523.5 ; 4280,-726.83 4280,-523.5 ; 4902,-1140 4902,-937.17
  text "COMPONENTS MARKED 'DNP' SHOULD NOT BE POPULATED." at 1153.5,-318.5 h60
  text "ASSEMBLY VARIANT:" at 1153,-434 h60
  text ".VariantName" at 2189,-434 h60
  text "PCB VIEWED FROM TOP SIDE" at -228.5,-655.67 h60
  text "BOARD #:" at 2248,-655.67 h60
  text ".PRJ_Number" at 2793.5,-655.67 h60
  text "REV:" at 3638,-655.67 h60
  text ".PCB_Rev" at 3929.5,-655.67 h60
  text "SVN REV:" at 4476,-655.67 h60
  text ".VersionControl_RevNumber" at 4982,-655.67 h60
  text "TID #:" at 2248,-859 h60
  text ".TID" at 2793.5,-859 h60
  text "PLOT NAME =" at -228.5,-1064.34 h60
  text ".plot_File_Name" at 577,-1064.34 h60
  text "GENERATED    :" at 2250,-1064.34 h60
  text ".Print_Date" at 3119.5,-1064.34 h60
  text ".Print_Time" at 3848.5,-1064.34 h60
  text "TEXAS INSTRUMENTS" at 5113,-1064.34 h60
M6 Assembly Bottom:
  lines w10: -292.5,-727.33 6309.5,-727.33 ; -290.5,-930.67 6309.5,-930.67 ; 1115.5,-1140.5 1115.5,-937.67 ; 1737.5,-727.33 1737.5,-524 ; 2577.5,-727.33 2577.5,-524 ; 3844.5,-1134 3844.5,-524 ; 4733.5,-1134 6309,-1134 6309,-524 -292.5,-524 -292.5,-1134 2304.5,-1134 6309.5,-1134 6309.5,-524
  text "COMPONENTS MARKED 'DNP' SHOULD NOT BE POPULATED." at 6102,-318 h60
  text ".VariantName" at 5058,-434 h60
  text "ASSEMBLY VARIANT:" at 6097,-434 h60
  text ".VersionControl_RevNumber" at 1035.5,-656.17 h60
  text "SVN REV:" at 1541.5,-656.17 h60
  text ".PCB_Rev" at 2088,-656.17 h60
  text "REV:" at 2379.5,-656.17 h60
  text ".PRJ_Number" at 3224,-656.17 h60
  text "BOARD #:" at 3769.5,-656.17 h60
  text "PCB VIEWED FROM BOTTOM SIDE" at 6246,-656.17 h60
  text ".TID" at 3224,-859.5 h60
  text "TID #:" at 3769.5,-859.5 h60
  text "TEXAS INSTRUMENTS" at 904.5,-1064.84 h60
  text ".Print_Time" at 2169,-1064.84 h60
  text ".Print_Date" at 2898,-1064.84 h60
  text "GENERATED    :" at 3767.5,-1064.84 h60
  text ".plot_File_Name" at 5440.5,-1064.84 h60
  text "PLOT NAME =" at 6246,-1064.84 h60
M9 Title Sheet:
  drawing of 57 lines, arcs and shapes, not listed
  text "1" at 739.84,8036.5 h70
  text "2" at 3235.5,8036.5 h70
  text "3" at 5724.84,8036.5 h70
  text "4" at 8231.51,8036.5 h70
  text "5" at 10730.5,8036.5 h70
  text "6" at 13235.5,8036.5 h70
  text "A" at -416.5,6893.5 h70
  text "A" at 14383.5,6893.5 h70
  text "B" at -416.5,4513.5 h70
  text "B" at 14383.5,4513.5 h70
  text "C" at -416.5,2138.5 h70
  text "C" at 14383.5,2138.5 h70
  text "PROJECT TITLE:" at 11343.5,277.5 h45
  text ".PRJ_Title" at 11393.5,144.17 h70
  text "DESIGNED FOR:" at 11343.5,-23.5 h45
  text ".PRJ_Customer" at 11393.5,-163.5 h70
  text "D" at -416.5,-231.5 h70
  text "D" at 14383.5,-231.5 h70
  text "FILE NAME:" at 11343.5,-323.5 h45
  text ".PCB_File_Name_No_Path" at 11393.5,-443.5 h70
  text "Texas Instruments (TI) and/or its licensors do not warrant the accuracy or completeness of this specification" at 6374,-605.34 h45
  text "ENGINEER:" at 11343.5,-613.5 h45
  text "LAYOUT BY:" at 12848.5,-613.5 h45
  text "or any information contained therein. TI and/or its licensors do not warrant that this design will meet" at 6329.01,-718 h45
  text ".PRJ_Engineer" at 11393.5,-768.49 h70
  text ".PCB_Layout" at 12899,-768.49 h70
  text "the specifications, will be suitable for your application or fit for any particular purpose, or will operate in" at 6329.01,-830.67 h45
  text ".Layer_Name" at 577,-858.49 h60
  text "ALTIUM DESIGNER VERSION:" at 12848.5,-923.5 h45
  text "an implementation. TI and/or its licensors do not warrant that the design is production worthy. You should" at 6329.01,-943.33 h45
  text "completely validate and test your design implementation to confirm the system functionality for your application." at 6374,-1056 h45
  text ".print_Scale" at 11393.5,-1056.83 h70
  text ".Application_BuildNumber" at 12899,-1056.83 h70
  text "1" at 739.84,-1263.5 h70
  text "2" at 3235.5,-1263.5 h70
  text "3" at 5724.84,-1263.5 h70
  text "4" at 8231.51,-1263.5 h70
  text "5" at 10730.5,-1263.5 h70
  text "6" at 13235.5,-1263.5 h70
M10 Fab Notes:
  drawing of 173 lines, arcs and shapes, not listed
  text "DESIGN INFORMATION" at 12378.02,6201 h60
  text "MIN. TRACK WIDTH:" at 11733.46,6021 h60
  text "8" at 12829.7,6021 h60
  text "MIL" at 12984.46,6021 h60
  text "MIN. CLEARANCE:" at 11733.46,5889 h60
  text "0.2" at 12769.7,5889 h60
  text "mm" at 12984.46,5889 h60
  text "MIN. VIA PAD SIZE:" at 11733.46,5757 h60
  text "24" at 12799.71,5757 h60
  text "MIL" at 12984.46,5757 h60
  text "0.05mm (2MIL)" at 12428.46,5615.29 h60
  text "MINIMUM ANNULAR RING" at 11404.23,5611 h60
  text "EXTERNAL" at 13136.46,5611 h60
  text "PER" at 11604.23,5493 h60
  text "IPC-D-275 CLASS 2 LEVEL C" at 11824.23,5493 h60
  text "MIL, HOLES" at 13312.46,5380.71 h60
  text "+/-" at 12920,5380 h60
  text "+/-" at 13774,5380 h60
  text "REGISTRATION TOLERANCES:" at 11404.23,5375 h60
  text "METAL" at 12604,5375 h60
  text "5" at 13180.2,5375 h60
  text "3" at 14013.2,5375 h60
  text "MIL" at 14129.46,5375 h60
  text "+/-" at 13774,5262 h60
  text "HOLE SIZE TOLERANCE (UNLESS OTHERWISE SPECIFIED):" at 11404.23,5257 h60
  text "3" at 14013.2,5257 h60
  text "MIL" at 14129.46,5257 h60
  text "MATERIAL:" at 11329.46,5047.54 h60
  text "FR-4 High Tg" at 12315.9,4907.21 h60
  text "FR-408" at 11750.46,4898.64 h60
  text "OTHER" at 13238.46,4898.64 h60
  text "X" at 12161,4895 h60
  text "62 MIL (1.6mm) +/-10%" at 12070.56,4735.92 h60
  text "THICKNESS:" at 11404.23,4731.64 h60
  text "X" at 11942.4,4731.64 h60
  text "OTHER" at 13355.46,4731.64 h60
  text "TOLERANCE:" at 11404.23,4573.64 h60
  text "X" at 12243.53,4573.64 h60
  text "ANSI IPC-6012 TYPE 3 CLASS 2" at 12430.48,4573.64 h60
  text "OTHER +/-" at 12430.46,4417.64 h60
  text "BOW & TWIST:" at 11404.23,4260.64 h60
  text "X" at 12243.53,4260.64 h60
  text "ANSI IPC-6012 TYPE 3 CLASS 2" at 12430.48,4260.64 h60
  text "OTHER +/-" at 12430.46,4102.13 h60
  text "DRILLING:" at 11329.46,3963.64 h60
  text "REFERENCE:" at 11404.23,3846.64 h60
  text "X" at 12052.46,3846.64 h60
  text "AS SHOWN" at 12239.46,3846.64 h60
  text "X" at 12953.46,3846.64 h60
  text "NC_DRILL FILES" at 13090.46,3846.64 h60
  text "PTH COPPER THICKNESS:" at 11404.23,3688.64 h60
  text "X" at 12534.46,3688.64 h60
  text "20-30 um" at 12671.46,3688.64 h60
  text "OTHER" at 13388.46,3688.64 h60
  text "BOARD FINISH:" at 11329.46,3529.64 h60
  text "SILKSCREEN:" at 11484.68,3411.64 h60
  text "X" at 12433.46,3411.64 h60
  text "TOP" at 12559.46,3411.64 h60
  text "X" at 12943.46,3411.64 h60
  text "BOTTOM" at 13070.46,3411.64 h60
  text "SILKSCREEN COLOR:" at 11484.68,3244.64 h60
  text "X" at 12432.42,3244.64 h60
  text "WHITE" at 12559.46,3244.64 h60
  text "OTHER" at 13070.46,3244.64 h60
  text "X" at 12563.42,3085.44 h60
  text "GREEN" at 12690.46,3085.44 h60
  text "OTHER" at 13308.46,3085.44 h60
  text "SOLDER RESIST COLOR:" at 11484.68,3074.64 h60
  text "X" at 12563.42,2915.44 h60
  text "MATTE" at 12690.46,2915.44 h60
  text "SEMI-GLOSS" at 13308,2914.8 h60
  text "IMMERSION GOLD (ENIG)" at 12390.46,2726.92 h60
  text "ENEPIG" at 13728,2723.64 h60
  text "SURFACE FINISH:" at 11329.46,2722.64 h60
  text "X" at 12203.51,2722.64 h60
  text "IMM. TIN/SILVER OR EQUIV" at 11659,2565.64 h60
  text "OTHER" at 13090.46,2565.64 h60
  text "ARRAY/PANEL:" at 11329.46,2386.64 h60
  text "CUT AND TRIM PER M1 BOARD OUTLINE" at 12390.46,2382.35 h60
  text "N.C. ROUTE" at 12390.46,2230.64 h60
  text "X" at 13069.46,2230.64 h60
  text "V. SCORE" at 13256.46,2230.64 h60
  text "CERTIFICATION:" at 11329.46,2093.64 h60
  text "MATERIALS AND WORKMANSHIP FOR ALL PCBS" at 12054.46,2093.64 h60
  text "TO MEET OR EXCEED THE REQUIREMENTS OF:" at 12054.46,1995.64 h60
  text "X" at 11680.96,1859.13 h60
  text "ANSI IPC-A-600F CLASS ->" at 11819.96,1859.13 h60
  text "X" at 13459.02,1859.13 h60
  text "2" at 13577.96,1859.14 h60
  text "1" at 13262.96,1857.64 h60
  text "3" at 13931.96,1857.64 h60
  text "X" at 12495.02,1699.64 h60
  text "RoHS" at 12631.96,1699.64 h60
  text "OTHER" at 13276.36,1699.64 h60
  text "PER ORDER" at 13673.42,1699.64 h60
  text "ALL BOARDS MUST MEET OR EXCEED UL94-V0 REQUIREMENTS." at 11357,1534 h60
  text "PCB MUST BEAR THE UL94V-0 UL REGISTERED MATERIAL ID NUMBER" at 11357,1414 h60
  text "ADDITIONAL REQUIREMENTS:" at 11329.46,1240.64 h60
  text "MICROSECTION:" at 11404.23,1125.64 h60
  text "YES" at 12309.96,1125.64 h60
  text "REQUIRED" at 13171.46,969.49 h60
  text "BARE BOARD ELEC. TEST:" at 11404.23,966.64 h60
  text "NONE" at 12709.96,966.64 h60
  text "X" at 13044.46,966.64 h60
  text "PER ORDER" at 13763.46,966.64 h60
  text ".Layer_Name" at 577,-858.49 h60
M11 Gerber Information:
  lines w10: -292,-930.17 6308,-930.17 ; -292,-726.83 6310,-726.83 ; -292,-523.5 -292,-1133.5 3713,-1133.5 6310,-1133.5 6310,-523.5 -291.5,-523.5 -291.5,-1133.5 1284,-1133.5 ; 2173,-1133.5 2173,-523.5 ; 3440,-726.83 3440,-523.5 ; 4280,-726.83 4280,-523.5 ; 4902,-1140 4902,-937.17
  text "ALL ARTWORK VIEWED FROM TOP SIDE" at -228.5,-655.67 h60
  text "BOARD #:" at 2248,-655.67 h60
  text ".PRJ_Number" at 2793.5,-655.67 h60
  text "REV:" at 3638,-655.67 h60
  text ".PCB_Rev" at 3929.5,-655.67 h60
  text "SVN REV:" at 4476,-655.67 h60
  text ".VersionControl_RevNumber" at 4982,-655.67 h60
  text "LAYER NAME =" at -228.5,-858.49 h60
  text "TID #:" at 2248,-859 h60
  text ".TID" at 2793.5,-859 h60
  text "PLOT NAME =" at -228.5,-1064.34 h60
  text ".plot_File_Name" at 577,-1064.34 h60
  text "GENERATED    :" at 2250,-1064.34 h60
  text ".Print_Date" at 3119.5,-1064.34 h60
  text ".Print_Time" at 3848.5,-1064.34 h60
  text "TEXAS INSTRUMENTS" at 5113,-1064.34 h60
M12 Stackup:
  drawing of 191 lines, arcs and shapes, not listed
  text "Layer" at 9790.34,7830 h60
  text "Name" at 10200.26,7830 h60
  text "Material" at 11130,7830 h60
  text "Thickness" at 11989.77,7830 h60
  text "Constant" at 12639.6,7830 h60
  text "Board Layer Stack" at 13209.46,7830 h60
  text "1" at 9790.34,7710 h60
  text "Top Overlay" at 10200.26,7710 h60
  text "2" at 9790.34,7590 h60
  text "Top Solder" at 10200.26,7590 h60
  text "Solder Resist" at 11130,7590 h60
  text "0.40mil" at 11989.77,7590 h60
  text "3.5" at 12639.6,7590 h60
  text "3" at 9790.34,7470 h60
  text "Top Layer" at 10200.26,7470 h60
  text "Copper" at 11130,7470 h60
  text "1.40mil" at 11989.77,7470 h60
  text "4" at 9790.34,7350 h60
  text "Dielectric1" at 10200.26,7350 h60
  text "FR-4" at 11130,7350 h60
  text "59.20mil" at 11989.77,7350 h60
  text "4.8" at 12639.6,7350 h60
  text "5" at 9790.34,7230 h60
  text "Bottom Layer" at 10200.26,7230 h60
  text "Copper" at 11130,7230 h60
  text "1.40mil" at 11989.77,7230 h60
  text "6" at 9790.34,7110 h60
  text "Bottom Solder" at 10200.26,7110 h60
  text "Solder Resist" at 11130,7110 h60
  text "0.40mil" at 11989.77,7110 h60
  text "3.5" at 12639.6,7110 h60
  text "7" at 9790.34,6990 h60
  text "Bottom Overlay" at 10200.26,6990 h60
  text ".Layer_Name" at 577,-858.49 h60
M13 Component Bodies Top:
  text ".Layer_Name" at 577,-858.49 h60
M14 Component Bodies Bottom:
  text ".Layer_Name" at 577,-858.49 h60
M15 Courtyards Top:
  text ".Layer_Name" at 577,-858.49 h60
M16 Courtyards Bottom:
  text ".Layer_Name" at 577,-858.49 h60
Drill Drawing:
  circle w10: c2915.55,2087.86 r13.28
  circle w10: c2915.55,2087.86 r22.14
  circle w10: c2915.55,1390.5 r22.14
  lines w10: 2893.41,1467.98 2915.55,1479.05 2937.69,1467.98 2926.62,1490.12 2937.69,1512.26 2915.55,1501.19 2893.41,1512.26 2904.48,1490.12 2893.41,1467.98 ; 2893.41,1567.61 2937.69,1567.61 2937.69,1611.88 2893.41,1611.88 2893.41,1567.61 ; 2893.41,1678.3 2904.48,1678.3 2915.55,1667.23 2926.62,1678.3 2937.69,1678.3 2926.62,1689.37 2937.69,1700.44 2926.62,1700.44 2915.55,1711.51 2904.48,1700.44 2893.41,1700.44 2904.48,1689.37 2893.41,1678.3 ; 2893.41,1777.92 2904.48,1777.92 2904.48,1766.85 2926.62,1766.85 2926.62,1777.92 2937.69,1777.92 2937.69,1800.06 2926.62,1800.06 2926.62,1811.13 2904.48,1811.13 2904.48,1800.06 2893.41,1800.06 2893.41,1777.92 ; 2893.41,1910.75 2937.69,1910.75 2915.55,1866.47 2893.41,1910.75 ; 2893.41,2010.37 2937.69,2010.37 2915.55,1966.1 2893.41,2010.37 ; 2893.41,2165.34 2937.69,2165.34 2937.69,2209.62 2893.41,2209.62 2893.41,2165.34 ; 2893.41,2276.03 2904.48,2276.03 2915.55,2264.96 2926.62,2276.03 2937.69,2276.03 2926.62,2287.1 2937.69,2298.17 2926.62,2298.17 2915.55,2309.24 2904.48,2298.17 2893.41,2298.17 2904.48,2287.1 2893.41,2276.03 ; 2893.41,2364.59 2893.41,2375.66 2904.48,2386.72 2893.41,2397.79 2893.41,2408.86 2904.48,2408.86 2915.55,2397.79 2926.62,2408.86 2937.69,2408.86 2937.69,2397.79 2926.62,2386.72 2937.69,2375.66 2937.69,2364.59 2926.62,2364.59 2915.55,2375.66 2904.48,2364.59 2893.41,2364.59 ; 2902.26,1901.9 2928.83,1901.9 2915.55,1875.33 2902.26,1901.9 ; 2902.26,2174.2 2928.83,2174.2 2928.83,2200.76 2902.26,2200.76 2902.26,2174.2 ; 2902.26,2280.46 2908.91,2280.46 2915.55,2273.82 2922.19,2280.46 2928.83,2280.46 2922.19,2287.1 2928.83,2293.74 2922.19,2293.74 2915.55,2300.38 2908.91,2293.74 2902.26,2293.74 2908.91,2287.1 2902.26,2280.46
  lines w12: 2852.65,1338.48 5965.59,1338.48 ; 2852.65,2434.32 5965.59,2434.32 ; 3168.28,1238.85 3168.28,2533.94 ; 3485.47,1238.85 3485.47,2533.94 ; 4107.21,1238.85 4107.21,2533.94 ; 4351.53,1238.85 4351.53,2533.94 ; 4711.87,1238.85 4711.87,2533.94 ; 5421.38,1238.85 5421.38,2533.94 ; 2852.65,1238.85 5965.59,1238.85 5965.59,2533.94 2852.65,2533.94 2852.65,1238.85
  text "Symbol" at 2912.42,2464.21 h72
  text "Quantity" at 3198.17,2464.21 h72
  text "Finished Hole Size" at 3515.35,2464.21 h72
  text "Plated" at 4137.1,2464.21 h72
  text "Hole Type" at 4381.42,2464.21 h72
  text "Drill Layer Pair" at 4741.76,2464.21 h72
  text "Hole Tolerance" at 5451.27,2464.21 h72
  text "2" at 3198.17,2364.59 h60
  text "66.93mil (1.700mm)" at 3515.35,2364.59 h60
  text "NPTH" at 4137.1,2364.59 h60
  text "Round" at 4381.42,2364.59 h60
  text "Top Layer - Bottom Layer" at 4741.76,2364.59 h60
  text "14" at 3198.17,2264.96 h60
  text "8.00mil (0.203mm)" at 3515.35,2264.96 h60
  text "PTH" at 4137.1,2264.96 h60
  text "Round" at 4381.42,2264.96 h60
  text "Top Layer - Bottom Layer" at 4741.76,2264.96 h60
  text "33" at 3198.17,2165.34 h60
  text "16.00mil (0.406mm)" at 3515.35,2165.34 h60
  text "PTH" at 4137.1,2165.34 h60
  text "Round" at 4381.42,2165.34 h60
  text "Top Layer - Bottom Layer" at 4741.76,2165.34 h60
  text "1" at 3198.17,2065.72 h60
  text "28.00mil (0.711mm)" at 3515.35,2065.72 h60
  text "PTH" at 4137.1,2065.72 h60
  text "Round" at 4381.42,2065.72 h60
  text "Top Layer - Bottom Layer" at 4741.76,2065.72 h60
  text "6" at 3198.17,1966.1 h60
  text "40.00mil (1.016mm)" at 3515.35,1966.1 h60
  text "PTH" at 4137.1,1966.1 h60
  text "Round" at 4381.42,1966.1 h60
  text "Top Layer - Bottom Layer" at 4741.76,1966.1 h60
  text "2" at 3198.17,1866.47 h60
  text "40.16mil (1.020mm)" at 3515.35,1866.47 h60
  text "PTH" at 4137.1,1866.47 h60
  text "Round" at 4381.42,1866.47 h60
  text "Top Layer - Bottom Layer" at 4741.76,1866.47 h60
  text "3" at 3198.17,1766.85 h60
  text "50.00mil (1.270mm)" at 3515.35,1766.85 h60
  text "PTH" at 4137.1,1766.85 h60
  text "Round" at 4381.42,1766.85 h60
  text "Top Layer - Bottom Layer" at 4741.76,1766.85 h60
  text "2" at 3198.17,1667.23 h60
  text "51.18mil (1.300mm)" at 3515.35,1667.23 h60
  text "PTH" at 4137.1,1667.23 h60
  text "Round" at 4381.42,1667.23 h60
  text "Top Layer - Bottom Layer" at 4741.76,1667.23 h60
  text "4" at 3198.17,1567.61 h60
  text "52.00mil (1.321mm)" at 3515.35,1567.61 h60
  text "PTH" at 4137.1,1567.61 h60
  text "Round" at 4381.42,1567.61 h60
  text "Top Layer - Bottom Layer" at 4741.76,1567.61 h60
  text "8" at 3198.17,1467.98 h60
  text "86.61mil (2.200mm)" at 3515.35,1467.98 h60
  text "PTH" at 4137.1,1467.98 h60
  text "Round" at 4381.42,1467.98 h60
  text "Top Layer - Bottom Layer" at 4741.76,1467.98 h60
  text "4" at 3198.17,1368.36 h60
  text "125.98mil (3.200mm)" at 3515.35,1368.36 h60
  text "PTH" at 4137.1,1368.36 h60
  text "Round" at 4381.42,1368.36 h60
  text "Top Layer - Bottom Layer" at 4741.76,1368.36 h60
  text "79 Total" at 3198.17,1268.74 h60
  text ".Layer_Name" at 577,-858.49 h60
M17 Embedded Cavity:
  text ".Layer_Name" at 577,-858.49 h60
M18 Embedded Assembly:
  text ".Layer_Name" at 577,-858.49 h60
M19 Embedded Keepout:
  text ".Layer_Name" at 577,-858.49 h60

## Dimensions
0,0 to 2500,0 on M2 Board Dimensions
0,3000 to 2500,0 on M2 Board Dimensions
0,-400 to 1000,-400 on M2 Board Dimensions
